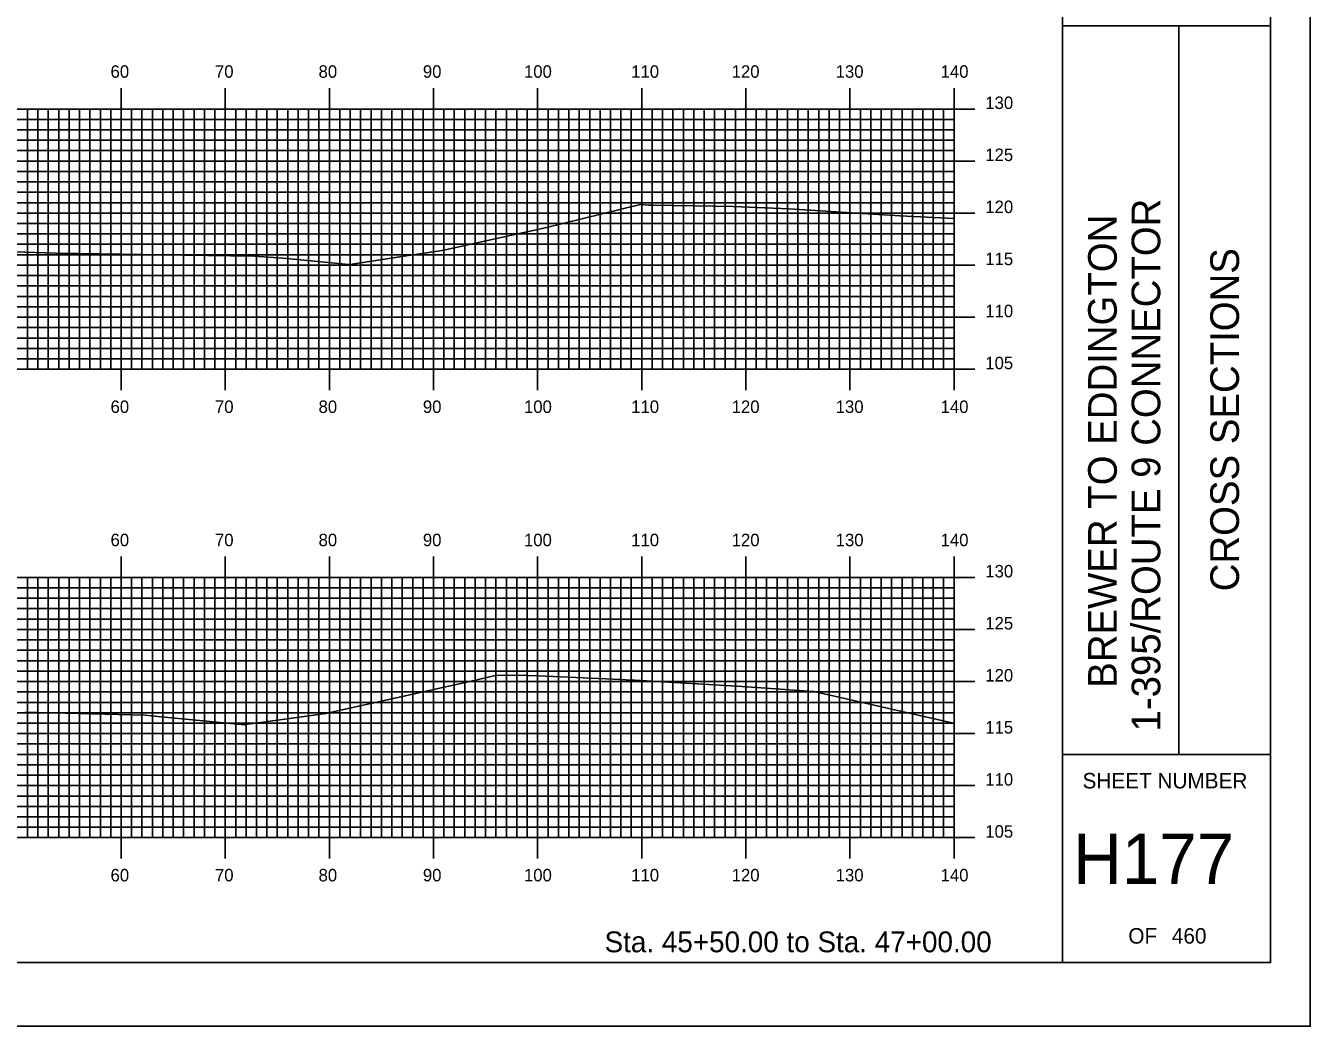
# Model space of a CAD drawing. Extents: x 1754314 to 1754654, y 442591 to 442811.
# Drawn here: x 1754530.8 to 1754654.2, y 442590.5 to 442686.7 of the extents above; entities that cross this region are included whole.
import ezdxf

# ---------------------------------------------------------------- set-up
doc = ezdxf.new("R2010")
doc.units = 0
for name, color, linetype in [('BORDER', 7, 'Continuous'), ('H_V ANNOTATION', 7, 'Continuous'), ('M_Roadway_Centerline', 7, 'Continuous'), ('MAJOR', 7, 'Continuous'), ('MINOR', 7, 'Continuous'), ('PLOT BOUNDARY', 7, 'Continuous'), ('S_Roadway_Centerline', 7, 'Continuous')]:
    doc.layers.add(name, color=color, linetype=linetype)

msp = doc.modelspace()

# ---------------------------------------------------------------- linework, layer by layer
at = {"layer": 'BORDER'}
for p, q in [((1754630.4, 442596.67), (1754630.4, 442806.67)), ((1754630.4, 442686.67), (1754650.4, 442686.67)), ((1754641.59, 442616.67), (1754641.59, 442686.67)), ((1754630.4, 442616.67), (1754650.4, 442616.67))]:
    msp.add_line(p, q, dxfattribs=at)
msp.add_lwpolyline([(1754330.4, 442596.67), (1754650.4, 442596.67), (1754650.4, 442806.67), (1754330.4, 442806.67)], close=True, dxfattribs=at)
at = {"layer": 'MAJOR'}
for p, q in [((1754540, 442680.67), (1754540, 442678.67)), ((1754550, 442680.67), (1754550, 442678.67)), ((1754560, 442680.67), (1754560, 442678.67)), ((1754570, 442680.67), (1754570, 442678.67)), ((1754580, 442680.67), (1754580, 442678.67)), ((1754590, 442680.67), (1754590, 442678.67)), ((1754600, 442680.67), (1754600, 442678.67)), ((1754610, 442680.67), (1754610, 442678.67)), ((1754620, 442680.67), (1754620, 442678.67)), ((1754340, 442678.67), (1754620, 442678.67)), ((1754340, 442678.67), (1754620, 442678.67)), ((1754540, 442653.67), (1754540, 442678.67)), ((1754550, 442653.67), (1754550, 442678.67)), ((1754560, 442653.67), (1754560, 442678.67)), ((1754570, 442653.67), (1754570, 442678.67)), ((1754580, 442653.67), (1754580, 442678.67)), ((1754590, 442653.67), (1754590, 442678.67)), ((1754600, 442653.67), (1754600, 442678.67)), ((1754610, 442653.67), (1754610, 442678.67)), ((1754622.01, 442678.67), (1754618, 442678.67)), ((1754620, 442653.67), (1754620, 442678.67)), ((1754620, 442653.67), (1754620, 442678.67)), ((1754622.01, 442673.67), (1754618, 442673.67)), ((1754340, 442668.67), (1754620, 442668.67)), ((1754622.01, 442668.67), (1754618, 442668.67)), ((1754340, 442663.67), (1754620, 442663.67)), ((1754622.01, 442663.67), (1754618, 442663.67)), ((1754340, 442658.67), (1754620, 442658.67)), ((1754622.01, 442658.67), (1754618, 442658.67)), ((1754340, 442653.67), (1754620, 442653.67)), ((1754340, 442653.67), (1754620, 442653.67)), ((1754540, 442651.66), (1754540, 442653.67)), ((1754550, 442651.66), (1754550, 442653.67)), ((1754560, 442651.66), (1754560, 442653.67)), ((1754570, 442651.66), (1754570, 442653.67)), ((1754580, 442651.66), (1754580, 442653.67)), ((1754590, 442651.66), (1754590, 442653.67)), ((1754600, 442651.66), (1754600, 442653.67)), ((1754610, 442651.66), (1754610, 442653.67)), ((1754622.01, 442653.67), (1754618, 442653.67)), ((1754620, 442651.66), (1754620, 442653.67)), ((1754540, 442635.67), (1754540, 442633.67)), ((1754550, 442635.67), (1754550, 442633.67)), ((1754560, 442635.67), (1754560, 442633.67)), ((1754570, 442635.67), (1754570, 442633.67)), ((1754580, 442635.67), (1754580, 442633.67)), ((1754590, 442635.67), (1754590, 442633.67)), ((1754600, 442635.67), (1754600, 442633.67)), ((1754610, 442635.67), (1754610, 442633.67)), ((1754620, 442635.67), (1754620, 442633.67)), ((1754340, 442633.67), (1754620, 442633.67)), ((1754340, 442633.67), (1754620, 442633.67)), ((1754540, 442608.67), (1754540, 442633.67)), ((1754550, 442608.67), (1754550, 442633.67)), ((1754560, 442608.67), (1754560, 442633.67)), ((1754570, 442608.67), (1754570, 442633.67)), ((1754580, 442608.67), (1754580, 442633.67)), ((1754590, 442608.67), (1754590, 442633.67)), ((1754600, 442608.67), (1754600, 442633.67)), ((1754610, 442608.67), (1754610, 442633.67)), ((1754622.01, 442633.67), (1754618, 442633.67)), ((1754620, 442608.67), (1754620, 442633.67)), ((1754620, 442608.67), (1754620, 442633.67)), ((1754340, 442628.67), (1754620, 442628.67)), ((1754622.01, 442628.67), (1754618, 442628.67)), ((1754340, 442623.67), (1754620, 442623.67)), ((1754622.01, 442623.67), (1754618, 442623.67)), ((1754340, 442618.67), (1754620, 442618.67)), ((1754622.01, 442618.67), (1754618, 442618.67)), ((1754340, 442613.67), (1754620, 442613.67)), ((1754622.01, 442613.67), (1754618, 442613.67)), ((1754340, 442608.67), (1754620, 442608.67)), ((1754340, 442608.67), (1754620, 442608.67)), ((1754540, 442606.66), (1754540, 442608.67)), ((1754550, 442606.66), (1754550, 442608.67)), ((1754560, 442606.66), (1754560, 442608.67)), ((1754570, 442606.66), (1754570, 442608.67)), ((1754580, 442606.66), (1754580, 442608.67)), ((1754590, 442606.66), (1754590, 442608.67)), ((1754600, 442606.66), (1754600, 442608.67)), ((1754610, 442606.66), (1754610, 442608.67)), ((1754622.01, 442608.67), (1754618, 442608.67)), ((1754620, 442606.66), (1754620, 442608.67))]:
    msp.add_line(p, q, dxfattribs=at)
at = {"layer": 'MINOR'}
for p, q in [((1754340, 442677.67), (1754620, 442677.67)), ((1754531, 442653.67), (1754531, 442678.67)), ((1754532, 442653.67), (1754532, 442678.67)), ((1754533, 442653.67), (1754533, 442678.67)), ((1754534, 442653.67), (1754534, 442678.67)), ((1754535, 442653.67), (1754535, 442678.67)), ((1754536, 442653.67), (1754536, 442678.67)), ((1754537, 442653.67), (1754537, 442678.67)), ((1754538, 442653.67), (1754538, 442678.67)), ((1754539, 442653.67), (1754539, 442678.67)), ((1754541, 442653.67), (1754541, 442678.67)), ((1754542, 442653.67), (1754542, 442678.67)), ((1754543, 442653.67), (1754543, 442678.67)), ((1754544, 442653.67), (1754544, 442678.67)), ((1754545, 442653.67), (1754545, 442678.67)), ((1754546, 442653.67), (1754546, 442678.67)), ((1754547, 442653.67), (1754547, 442678.67)), ((1754548, 442653.67), (1754548, 442678.67)), ((1754549, 442653.67), (1754549, 442678.67)), ((1754551, 442653.67), (1754551, 442678.67)), ((1754552, 442653.67), (1754552, 442678.67)), ((1754553, 442653.67), (1754553, 442678.67)), ((1754554, 442653.67), (1754554, 442678.67)), ((1754555, 442653.67), (1754555, 442678.67)), ((1754556, 442653.67), (1754556, 442678.67)), ((1754557, 442653.67), (1754557, 442678.67)), ((1754558, 442653.67), (1754558, 442678.67)), ((1754559, 442653.67), (1754559, 442678.67)), ((1754561, 442653.67), (1754561, 442678.67)), ((1754562, 442653.67), (1754562, 442678.67)), ((1754563, 442653.67), (1754563, 442678.67)), ((1754564, 442653.67), (1754564, 442678.67)), ((1754565, 442653.67), (1754565, 442678.67)), ((1754566, 442653.67), (1754566, 442678.67)), ((1754567, 442653.67), (1754567, 442678.67)), ((1754568, 442653.67), (1754568, 442678.67)), ((1754569, 442653.67), (1754569, 442678.67)), ((1754571, 442653.67), (1754571, 442678.67)), ((1754572, 442653.67), (1754572, 442678.67)), ((1754573, 442653.67), (1754573, 442678.67)), ((1754574, 442653.67), (1754574, 442678.67)), ((1754575, 442653.67), (1754575, 442678.67)), ((1754576, 442653.67), (1754576, 442678.67)), ((1754577, 442653.67), (1754577, 442678.67)), ((1754578, 442653.67), (1754578, 442678.67)), ((1754579, 442653.67), (1754579, 442678.67)), ((1754581, 442653.67), (1754581, 442678.67)), ((1754582, 442653.67), (1754582, 442678.67)), ((1754583, 442653.67), (1754583, 442678.67)), ((1754584, 442653.67), (1754584, 442678.67)), ((1754585, 442653.67), (1754585, 442678.67)), ((1754586, 442653.67), (1754586, 442678.67)), ((1754587, 442653.67), (1754587, 442678.67)), ((1754588, 442653.67), (1754588, 442678.67)), ((1754589, 442653.67), (1754589, 442678.67)), ((1754591, 442653.67), (1754591, 442678.67)), ((1754592, 442653.67), (1754592, 442678.67)), ((1754593, 442653.67), (1754593, 442678.67)), ((1754594, 442653.67), (1754594, 442678.67)), ((1754595, 442653.67), (1754595, 442678.67)), ((1754596, 442653.67), (1754596, 442678.67)), ((1754597, 442653.67), (1754597, 442678.67)), ((1754598, 442653.67), (1754598, 442678.67)), ((1754599, 442653.67), (1754599, 442678.67)), ((1754601, 442653.67), (1754601, 442678.67)), ((1754602, 442653.67), (1754602, 442678.67)), ((1754603, 442653.67), (1754603, 442678.67)), ((1754604, 442653.67), (1754604, 442678.67)), ((1754605, 442653.67), (1754605, 442678.67)), ((1754606, 442653.67), (1754606, 442678.67)), ((1754607, 442653.67), (1754607, 442678.67)), ((1754608, 442653.67), (1754608, 442678.67)), ((1754609, 442653.67), (1754609, 442678.67)), ((1754611, 442653.67), (1754611, 442678.67)), ((1754612, 442653.67), (1754612, 442678.67)), ((1754613, 442653.67), (1754613, 442678.67)), ((1754614, 442653.67), (1754614, 442678.67)), ((1754615, 442653.67), (1754615, 442678.67)), ((1754616, 442653.67), (1754616, 442678.67)), ((1754617, 442653.67), (1754617, 442678.67)), ((1754618, 442653.67), (1754618, 442678.67)), ((1754620, 442677.67), (1754618, 442677.67)), ((1754619, 442653.67), (1754619, 442678.67)), ((1754340, 442676.67), (1754620, 442676.67)), ((1754620, 442676.67), (1754618, 442676.67)), ((1754340, 442675.67), (1754620, 442675.67)), ((1754620, 442675.67), (1754618, 442675.67)), ((1754340, 442674.67), (1754620, 442674.67)), ((1754620, 442674.67), (1754618, 442674.67)), ((1754340, 442673.67), (1754620, 442673.67)), ((1754340, 442672.67), (1754620, 442672.67)), ((1754620, 442672.67), (1754618, 442672.67)), ((1754340, 442671.67), (1754620, 442671.67)), ((1754620, 442671.67), (1754618, 442671.67)), ((1754340, 442670.67), (1754620, 442670.67)), ((1754620, 442670.67), (1754618, 442670.67)), ((1754340, 442669.67), (1754620, 442669.67)), ((1754620, 442669.67), (1754618, 442669.67)), ((1754340, 442667.67), (1754620, 442667.67)), ((1754620, 442667.67), (1754618, 442667.67)), ((1754340, 442666.67), (1754620, 442666.67)), ((1754620, 442666.67), (1754618, 442666.67)), ((1754340, 442665.67), (1754620, 442665.67)), ((1754620, 442665.67), (1754618, 442665.67)), ((1754340, 442664.67), (1754620, 442664.67)), ((1754620, 442664.67), (1754618, 442664.67)), ((1754340, 442662.67), (1754620, 442662.67)), ((1754340, 442661.67), (1754620, 442661.67)), ((1754620, 442662.67), (1754618, 442662.67)), ((1754620, 442661.67), (1754618, 442661.67)), ((1754340, 442660.67), (1754620, 442660.67)), ((1754620, 442660.67), (1754618, 442660.67)), ((1754340, 442659.67), (1754620, 442659.67)), ((1754620, 442659.67), (1754618, 442659.67)), ((1754340, 442657.67), (1754620, 442657.67)), ((1754340, 442656.67), (1754620, 442656.67)), ((1754620, 442657.67), (1754618, 442657.67)), ((1754620, 442656.67), (1754618, 442656.67)), ((1754340, 442655.67), (1754620, 442655.67)), ((1754620, 442655.67), (1754618, 442655.67)), ((1754340, 442654.67), (1754620, 442654.67)), ((1754620, 442654.67), (1754618, 442654.67)), ((1754531, 442608.67), (1754531, 442633.67)), ((1754532, 442608.67), (1754532, 442633.67)), ((1754533, 442608.67), (1754533, 442633.67)), ((1754534, 442608.67), (1754534, 442633.67)), ((1754535, 442608.67), (1754535, 442633.67)), ((1754536, 442608.67), (1754536, 442633.67)), ((1754537, 442608.67), (1754537, 442633.67)), ((1754538, 442608.67), (1754538, 442633.67)), ((1754539, 442608.67), (1754539, 442633.67)), ((1754541, 442608.67), (1754541, 442633.67)), ((1754542, 442608.67), (1754542, 442633.67)), ((1754543, 442608.67), (1754543, 442633.67)), ((1754544, 442608.67), (1754544, 442633.67)), ((1754545, 442608.67), (1754545, 442633.67)), ((1754546, 442608.67), (1754546, 442633.67)), ((1754547, 442608.67), (1754547, 442633.67)), ((1754548, 442608.67), (1754548, 442633.67)), ((1754549, 442608.67), (1754549, 442633.67)), ((1754551, 442608.67), (1754551, 442633.67)), ((1754552, 442608.67), (1754552, 442633.67)), ((1754553, 442608.67), (1754553, 442633.67)), ((1754554, 442608.67), (1754554, 442633.67)), ((1754555, 442608.67), (1754555, 442633.67)), ((1754556, 442608.67), (1754556, 442633.67)), ((1754557, 442608.67), (1754557, 442633.67)), ((1754558, 442608.67), (1754558, 442633.67)), ((1754559, 442608.67), (1754559, 442633.67)), ((1754561, 442608.67), (1754561, 442633.67)), ((1754562, 442608.67), (1754562, 442633.67)), ((1754563, 442608.67), (1754563, 442633.67)), ((1754564, 442608.67), (1754564, 442633.67)), ((1754565, 442608.67), (1754565, 442633.67)), ((1754566, 442608.67), (1754566, 442633.67)), ((1754567, 442608.67), (1754567, 442633.67)), ((1754568, 442608.67), (1754568, 442633.67)), ((1754569, 442608.67), (1754569, 442633.67)), ((1754571, 442608.67), (1754571, 442633.67)), ((1754572, 442608.67), (1754572, 442633.67)), ((1754573, 442608.67), (1754573, 442633.67)), ((1754574, 442608.67), (1754574, 442633.67)), ((1754575, 442608.67), (1754575, 442633.67)), ((1754576, 442608.67), (1754576, 442633.67)), ((1754577, 442608.67), (1754577, 442633.67)), ((1754578, 442608.67), (1754578, 442633.67)), ((1754579, 442608.67), (1754579, 442633.67)), ((1754581, 442608.67), (1754581, 442633.67)), ((1754582, 442608.67), (1754582, 442633.67)), ((1754583, 442608.67), (1754583, 442633.67)), ((1754584, 442608.67), (1754584, 442633.67)), ((1754585, 442608.67), (1754585, 442633.67)), ((1754586, 442608.67), (1754586, 442633.67)), ((1754587, 442608.67), (1754587, 442633.67)), ((1754588, 442608.67), (1754588, 442633.67)), ((1754589, 442608.67), (1754589, 442633.67)), ((1754591, 442608.67), (1754591, 442633.67)), ((1754592, 442608.67), (1754592, 442633.67)), ((1754593, 442608.67), (1754593, 442633.67)), ((1754594, 442608.67), (1754594, 442633.67)), ((1754595, 442608.67), (1754595, 442633.67)), ((1754596, 442608.67), (1754596, 442633.67)), ((1754597, 442608.67), (1754597, 442633.67)), ((1754598, 442608.67), (1754598, 442633.67)), ((1754599, 442608.67), (1754599, 442633.67)), ((1754601, 442608.67), (1754601, 442633.67)), ((1754602, 442608.67), (1754602, 442633.67)), ((1754603, 442608.67), (1754603, 442633.67)), ((1754604, 442608.67), (1754604, 442633.67)), ((1754605, 442608.67), (1754605, 442633.67)), ((1754606, 442608.67), (1754606, 442633.67)), ((1754607, 442608.67), (1754607, 442633.67)), ((1754608, 442608.67), (1754608, 442633.67)), ((1754609, 442608.67), (1754609, 442633.67)), ((1754611, 442608.67), (1754611, 442633.67)), ((1754612, 442608.67), (1754612, 442633.67)), ((1754613, 442608.67), (1754613, 442633.67)), ((1754614, 442608.67), (1754614, 442633.67)), ((1754615, 442608.67), (1754615, 442633.67)), ((1754616, 442608.67), (1754616, 442633.67)), ((1754617, 442608.67), (1754617, 442633.67)), ((1754618, 442608.67), (1754618, 442633.67)), ((1754619, 442608.67), (1754619, 442633.67)), ((1754340, 442632.67), (1754620, 442632.67)), ((1754620, 442632.67), (1754618, 442632.67)), ((1754340, 442631.67), (1754620, 442631.67)), ((1754340, 442630.67), (1754620, 442630.67)), ((1754620, 442631.67), (1754618, 442631.67)), ((1754620, 442630.67), (1754618, 442630.67)), ((1754340, 442629.67), (1754620, 442629.67)), ((1754620, 442629.67), (1754618, 442629.67)), ((1754340, 442627.67), (1754620, 442627.67)), ((1754620, 442627.67), (1754618, 442627.67)), ((1754340, 442626.67), (1754620, 442626.67)), ((1754620, 442626.67), (1754618, 442626.67)), ((1754340, 442625.67), (1754620, 442625.67)), ((1754340, 442624.67), (1754620, 442624.67)), ((1754620, 442625.67), (1754618, 442625.67)), ((1754620, 442624.67), (1754618, 442624.67)), ((1754340, 442622.67), (1754620, 442622.67)), ((1754620, 442622.67), (1754618, 442622.67)), ((1754340, 442621.67), (1754620, 442621.67)), ((1754620, 442621.67), (1754618, 442621.67)), ((1754340, 442620.67), (1754620, 442620.67)), ((1754340, 442619.67), (1754620, 442619.67)), ((1754620, 442620.67), (1754618, 442620.67)), ((1754620, 442619.67), (1754618, 442619.67)), ((1754340, 442617.67), (1754620, 442617.67)), ((1754620, 442617.67), (1754618, 442617.67)), ((1754340, 442616.67), (1754620, 442616.67)), ((1754620, 442616.67), (1754618, 442616.67)), ((1754340, 442615.67), (1754620, 442615.67)), ((1754340, 442614.67), (1754620, 442614.67)), ((1754620, 442615.67), (1754618, 442615.67)), ((1754620, 442614.67), (1754618, 442614.67)), ((1754340, 442612.67), (1754620, 442612.67)), ((1754620, 442612.67), (1754618, 442612.67)), ((1754340, 442611.67), (1754620, 442611.67)), ((1754620, 442611.67), (1754618, 442611.67)), ((1754340, 442610.67), (1754620, 442610.67)), ((1754340, 442609.67), (1754620, 442609.67)), ((1754620, 442610.67), (1754618, 442610.67)), ((1754620, 442609.67), (1754618, 442609.67))]:
    msp.add_line(p, q, dxfattribs=at)
at = {"layer": 'PLOT BOUNDARY'}
msp.add_lwpolyline([(1754314.22, 442590.55), (1754654.22, 442590.55), (1754654.22, 442810.55), (1754314.22, 442810.55)], close=True, dxfattribs=at)
at = {"layer": 'S_Roadway_Centerline'}
for points in [[(1754526.71, 442665.03), (1754533.76, 442664.81), (1754546.06, 442664.64), (1754552.77, 442664.52), (1754555.55, 442664.33), (1754561.52, 442663.75), (1754561.97, 442663.74), (1754567.17, 442664.54), (1754570.82, 442665.07), (1754580.72, 442667.26), (1754589.85, 442669.5), (1754590.65, 442669.44), (1754591.14, 442669.44), (1754598.79, 442669.31), (1754604.14, 442669.09), (1754606.68, 442668.91), (1754610.65, 442668.66), (1754614.82, 442668.4), (1754620, 442668.14)], [(1754530.77, 442620.71), (1754542.29, 442620.44), (1754543.51, 442620.31), (1754551.86, 442619.52), (1754551.9, 442619.53), (1754553.38, 442619.73), (1754559.66, 442620.59), (1754573.61, 442623.71), (1754576.08, 442624.28), (1754578.89, 442624.24), (1754580.06, 442624.22), (1754587.25, 442623.9), (1754589.16, 442623.81), (1754589.34, 442623.81), (1754596.95, 442623.35), (1754599.18, 442623.21), (1754606.5, 442622.71), (1754606.52, 442622.71), (1754606.54, 442622.7), (1754619.67, 442619.74), (1754620, 442619.66)]]:
    msp.add_lwpolyline(points, dxfattribs=at)

# ---------------------------------------------------------------- texts
at = {"layer": 'BORDER'}
for s, p in [('1-395/ROUTE 9 CONNECTOR', (1754639.81, 442618.87)), ('BREWER TO EDDINGTON', (1754635.63, 442623.07)), ('CROSS SECTIONS', (1754647.37, 442632.34))]:
    msp.add_text(s, height=2.7557, rotation=90, dxfattribs=at).set_placement(p)
for s, height, p in [('SHEET NUMBER', 1.4905, (1754632.34, 442613.4)), ('H177', 4.839, (1754631.44, 442604.23)), ('OF', 1.491, (1754636.74, 442598.49)), ('460', 1.491, (1754640.92, 442598.49))]:
    msp.add_text(s, height=height, dxfattribs=at).set_placement(p)
at = {"layer": 'H_V ANNOTATION'}
for s, height, p in [('60', 1.2, (1754538.98, 442681.67)), ('70', 1.2, (1754549.01, 442681.67)), ('80', 1.2, (1754558.96, 442681.67)), ('90', 1.2, (1754568.98, 442681.67)), ('100', 1.2, (1754578.69, 442681.67)), ('110', 1.2, (1754588.99, 442681.67)), ('120', 1.2, (1754598.64, 442681.67)), ('130', 1.2, (1754608.63, 442681.67)), ('140', 1.2, (1754618.71, 442681.67)), ('130', 1.2, (1754623, 442678.67)), ('125', 1.2, (1754623, 442673.67)), ('120', 1.2, (1754623, 442668.67)), ('115', 1.2, (1754623, 442663.67)), ('110', 1.2, (1754623, 442658.67)), ('105', 1.2, (1754623, 442653.67)), ('60', 1.2, (1754538.98, 442649.47)), ('70', 1.2, (1754549.01, 442649.47)), ('80', 1.2, (1754558.96, 442649.47)), ('90', 1.2, (1754568.98, 442649.47)), ('100', 1.2, (1754578.69, 442649.47)), ('110', 1.2, (1754588.99, 442649.47)), ('120', 1.2, (1754598.64, 442649.47)), ('130', 1.2, (1754608.63, 442649.47)), ('140', 1.2, (1754618.71, 442649.47)), ('60', 1.2, (1754538.98, 442636.67)), ('70', 1.2, (1754549.01, 442636.67)), ('80', 1.2, (1754558.96, 442636.67)), ('90', 1.2, (1754568.98, 442636.67)), ('100', 1.2, (1754578.69, 442636.67)), ('110', 1.2, (1754588.99, 442636.67)), ('120', 1.2, (1754598.64, 442636.67)), ('130', 1.2, (1754608.63, 442636.67)), ('140', 1.2, (1754618.71, 442636.67)), ('130', 1.2, (1754623, 442633.67)), ('125', 1.2, (1754623, 442628.67)), ('120', 1.2, (1754623, 442623.67)), ('115', 1.2, (1754623, 442618.67)), ('110', 1.2, (1754623, 442613.67)), ('105', 1.2, (1754623, 442608.67)), ('60', 1.2, (1754538.98, 442604.47)), ('70', 1.2, (1754549.01, 442604.47)), ('80', 1.2, (1754558.96, 442604.47)), ('90', 1.2, (1754568.98, 442604.47)), ('100', 1.2, (1754578.69, 442604.47)), ('110', 1.2, (1754588.99, 442604.47)), ('120', 1.2, (1754598.64, 442604.47)), ('130', 1.2, (1754608.63, 442604.47)), ('140', 1.2, (1754618.71, 442604.47)), ('Sta. 45+50.00 to Sta. 47+00.00', 2.0004, (1754586.43, 442597.66))]:
    msp.add_text(s, height=height, dxfattribs=at).set_placement(p)
at = {"layer": 'M_Roadway_Centerline'}
for s, p in [('C', (1754604.13, 442669.09)), ('L', (1754604.14, 442669.08)), ('C', (1754589.34, 442623.81)), ('L', (1754589.34, 442623.81))]:
    msp.add_text(s, height=0.0146, dxfattribs=at).set_placement(p)

doc.saveas('drawing.dxf')
